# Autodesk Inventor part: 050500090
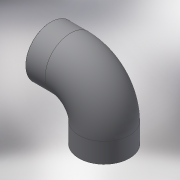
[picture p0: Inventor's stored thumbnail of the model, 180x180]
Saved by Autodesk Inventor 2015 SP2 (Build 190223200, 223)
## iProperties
Created: 2017-10
Part Number: 050500090
Material: Generic
Description: PLASSON 90° ELBOW-CEMENT PVC 90
Document SubType Name: Modeling
Designer: KIM
Density: 1 g/cm^3
Appearance: Default
Author: KIM
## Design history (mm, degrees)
derived "050500.ipt"
feature "Solid1::050500.ipt"
tag "TaggingFeature1"
body "Solid1"
other parameters: "d1" = 108, "d5" = 81, "d7" = 0.9, "d9" = 108, "d13" = 90 deg, "d18" = 49, "d19" = 90 deg, "d21" = 51, "d22" = 0, "d24" = 90 deg, "d26" = 81, "d27" = 90 deg, "E_" = 108, "H_" = 154, "l_" = 51, "Z_" = 49
